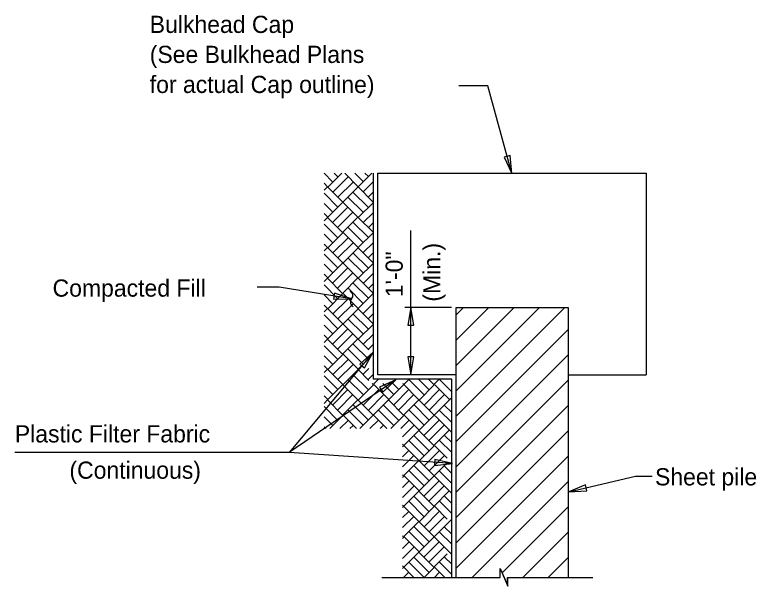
# Model space of a CAD drawing. Extents: x 0.4 to 30.4, y 0.1 to 19.4.
# Drawn here: x 8.54 to 15.06, y 14.4 to 19.42 of the extents above; entities that cross this region are included whole.
import ezdxf

# ---------------------------------------------------------------- set-up
doc = ezdxf.new("R2010")
doc.units = 0
for name, color, linetype in [('Dimension', 7, 'Continuous'), ('Miscellaneous', 7, 'Continuous'), ('Rebar', 7, 'Continuous'), ('SheetPileConc', 7, 'Continuous'), ('SheetPileConc_h', 7, 'Continuous'), ('TextStructures', 7, 'Continuous')]:
    doc.layers.add(name, color=color, linetype=linetype)

msp = doc.modelspace()

# ---------------------------------------------------------------- linework, layer by layer
at = {"layer": 'Dimension'}
for p, q in [((12.0243, 16.2579), (12.0243, 17.526)), ((12.3831, 16.8485), (11.9719, 16.8485)), ((11.8922, 16.2141), (10.9542, 15.5723)), ((12.3913, 15.4765), (10.9542, 15.5723)), ((11.7699, 14.4758), (12.738, 14.4758)), ((12.9487, 14.4758), (13.6252, 14.4758))]:
    msp.add_line(p, q, dxfattribs=at)
for points in [[(12.913, 18.0264), (12.7019, 18.7989), (12.4481, 18.7989)], [(11.5034, 16.9244), (10.8661, 17.0282), (10.6716, 17.0282)], [(11.6942, 16.4565), (10.9542, 15.5723), (8.5393, 15.5723)], [(13.4152, 15.2266), (14.0033, 15.3663), (14.1471, 15.3663)], [(12.738, 14.4758), (12.8099, 14.4758), (12.8099, 14.5539), (12.8768, 14.4028), (12.8768, 14.4758), (12.9487, 14.4758)], [(12.7383, 14.4758), (12.8108, 14.4758), (12.8108, 14.5533), (12.8446, 14.4758), (12.8783, 14.3983), (12.8783, 14.4758), (12.9508, 14.4758)]]:
    msp.add_lwpolyline(points, dxfattribs=at)
for points in [[(12.913, 18.0264), (12.8979, 18.1841), (12.8468, 18.1703)], [(11.5034, 16.9244), (11.3535, 16.9757), (11.345, 16.9234)], [(12.0243, 16.8485), (11.9978, 16.6923), (12.0507, 16.6923)], [(11.6942, 16.4565), (11.5762, 16.3508), (11.6176, 16.3178)], [(12.0243, 16.2579), (12.0507, 16.4141), (11.9978, 16.4141)], [(11.8922, 16.2141), (11.7485, 16.1474), (11.7785, 16.1038)], [(12.3913, 15.4765), (12.2372, 15.513), (12.2338, 15.4601)], [(13.4152, 15.2267), (13.5733, 15.2372), (13.561, 15.2886)]]:
    msp.add_lwpolyline(points, close=True, dxfattribs=at)
for centre, start, end in [((11.4742, 16.9527), 316.04656, 67.77378), ((11.5327, 16.8962), 136.04656, 247.77378)]:
    msp.add_arc(centre, 0.0406, start, end, dxfattribs=at)
at = {"layer": 'Miscellaneous'}
for p, q in [((11.2621, 18.0293), (11.3361, 17.9553)), ((11.4162, 18.0298), (11.2947, 17.9082)), ((11.3499, 18.0298), (11.3803, 17.9994)), ((11.5624, 17.9114), (11.444, 18.0298)), ((11.6065, 17.9555), (11.5323, 18.0298)), ((11.6808, 18.0298), (11.5624, 17.9114)), ((11.6507, 17.9998), (11.6208, 18.0298)), ((11.4716, 17.9966), (11.3389, 17.8639)), ((11.5157, 17.9524), (11.383, 17.8198)), ((11.6952, 17.9559), (11.6065, 17.8673)), ((11.2919, 17.911), (11.2621, 17.9408)), ((11.2919, 17.911), (11.2621, 17.8812)), ((11.5594, 17.6434), (11.2947, 17.9082)), ((11.5596, 17.9086), (11.2948, 17.6438)), ((11.5596, 17.9086), (11.6952, 17.773)), ((11.3832, 17.7322), (11.2621, 17.8533)), ((11.4712, 17.8202), (11.6037, 17.6877)), ((11.5153, 17.8643), (11.6478, 17.7318)), ((11.6952, 17.8673), (11.6506, 17.8231)), ((11.3389, 17.688), (11.2621, 17.7648)), ((11.6952, 17.7736), (11.5622, 17.6406)), ((11.471, 17.7318), (11.3389, 17.5997)), ((11.5152, 17.6877), (11.383, 17.5556)), ((11.6952, 17.6851), (11.6065, 17.5963)), ((11.2948, 17.6438), (11.2621, 17.6766)), ((11.292, 17.641), (11.2621, 17.6111)), ((11.292, 17.641), (11.4246, 17.5085)), ((11.5594, 17.6434), (11.4273, 17.5113)), ((11.6952, 17.5077), (11.5622, 17.6406)), ((11.2621, 17.5824), (11.3803, 17.4643)), ((11.6065, 17.4204), (11.4742, 17.5526)), ((11.6507, 17.4647), (11.5185, 17.5969)), ((11.6952, 17.5964), (11.6506, 17.5522)), ((11.2621, 17.4942), (11.3361, 17.4201)), ((11.4273, 17.5057), (11.2947, 17.3731)), ((11.5624, 17.3762), (11.4301, 17.5085)), ((11.6952, 17.5091), (11.5624, 17.3762)), ((11.4716, 17.4614), (11.3389, 17.3288)), ((11.6952, 17.4209), (11.6065, 17.3321)), ((11.2919, 17.3758), (11.2621, 17.4056)), ((11.2919, 17.3758), (11.2621, 17.3461)), ((11.5594, 17.1083), (11.2947, 17.3731)), ((11.5596, 17.3735), (11.2948, 17.1087)), ((11.5157, 17.4173), (11.383, 17.2847)), ((11.5596, 17.3735), (11.6952, 17.2379)), ((11.3832, 17.1971), (11.2621, 17.3182)), ((11.5153, 17.3292), (11.6478, 17.1967)), ((11.6952, 17.3322), (11.6506, 17.288)), ((11.3389, 17.1529), (11.2621, 17.2297)), ((11.4712, 17.2851), (11.6037, 17.1525)), ((11.6952, 17.2385), (11.5622, 17.1055)), ((11.471, 17.1967), (11.3389, 17.0646)), ((11.2948, 17.1087), (11.2621, 17.1414)), ((11.292, 17.1059), (11.2621, 17.076)), ((11.292, 17.1059), (11.4246, 16.9734)), ((11.5152, 17.1525), (11.383, 17.0205)), ((11.5594, 17.1083), (11.4273, 16.9762)), ((11.6952, 16.9725), (11.5622, 17.1055)), ((11.6952, 17.1499), (11.6065, 17.0612)), ((11.2621, 17.0473), (11.3803, 16.9291)), ((11.6507, 16.9295), (11.5185, 17.0618)), ((11.6952, 17.0613), (11.6506, 17.0171)), ((11.4273, 16.9706), (11.2947, 16.8379)), ((11.5624, 16.8411), (11.4301, 16.9734)), ((11.6065, 16.8853), (11.4742, 17.0175)), ((11.6945, 16.9732), (11.5624, 16.8411)), ((11.2621, 16.9591), (11.3361, 16.885)), ((11.4716, 16.9263), (11.3389, 16.7937)), ((11.2919, 16.8407), (11.2621, 16.8705)), ((11.2919, 16.8407), (11.2621, 16.8109)), ((11.5594, 16.5732), (11.2947, 16.8379)), ((11.5596, 16.8384), (11.2948, 16.5736)), ((11.5157, 16.8822), (11.383, 16.7495)), ((11.5596, 16.8384), (11.6952, 16.7027)), ((11.6952, 16.8858), (11.6065, 16.797)), ((12.4236, 16.5612), (12.7109, 16.8485)), ((12.4236, 16.3385), (12.9336, 16.8485)), ((12.4236, 16.1158), (13.1564, 16.8485)), ((12.4236, 15.8931), (13.3791, 16.8485)), ((12.4236, 16.7839), (12.4882, 16.8485)), ((11.3832, 16.662), (11.2621, 16.7831)), ((11.5153, 16.7941), (11.6478, 16.6616)), ((11.6952, 16.7971), (11.6506, 16.7529)), ((11.4712, 16.75), (11.6037, 16.6174)), ((11.6949, 16.703), (11.5622, 16.5704)), ((11.3389, 16.6177), (11.2621, 16.6946)), ((11.471, 16.6616), (11.3389, 16.5295)), ((12.4236, 15.6703), (13.408, 16.6547)), ((11.2948, 16.5736), (11.2621, 16.6063)), ((11.5152, 16.6174), (11.383, 16.4853)), ((11.5594, 16.5732), (11.4273, 16.441)), ((11.6952, 16.6148), (11.6065, 16.5261)), ((11.292, 16.5708), (11.2621, 16.5409)), ((11.2621, 16.5122), (11.3803, 16.394)), ((11.292, 16.5708), (11.4246, 16.4383)), ((11.6507, 16.3944), (11.5185, 16.5267)), ((11.6559, 16.4768), (11.5622, 16.5704)), ((11.6952, 16.5262), (11.6506, 16.482)), ((11.6065, 16.3501), (11.4742, 16.4824)), ((11.2621, 16.4239), (11.3361, 16.3499)), ((11.4273, 16.4355), (11.2947, 16.3028)), ((11.4716, 16.3912), (11.3389, 16.2585)), ((11.5624, 16.306), (11.4301, 16.4383)), ((11.6559, 16.3995), (11.5624, 16.306)), ((12.4236, 15.4475), (13.408, 16.4319)), ((11.2919, 16.3056), (11.2621, 16.3354)), ((11.5157, 16.3471), (11.383, 16.2144)), ((11.2919, 16.3056), (11.2621, 16.2758)), ((11.3832, 16.1269), (11.2621, 16.248)), ((11.5594, 16.038), (11.2947, 16.3028)), ((11.5596, 16.3032), (11.2948, 16.0384)), ((11.5153, 16.2589), (11.6478, 16.1264)), ((11.5596, 16.3032), (11.6559, 16.207)), ((11.6559, 16.3112), (11.6065, 16.2619)), ((11.6952, 16.2619), (11.6506, 16.2178)), ((11.4712, 16.2148), (11.6037, 16.0823)), ((11.7396, 16.2185), (11.6949, 16.1735)), ((12.01, 16.2185), (11.8299, 16.0384)), ((12.0026, 16.2185), (12.1388, 16.0823)), ((12.0909, 16.2185), (12.1829, 16.1264)), ((12.1794, 16.2185), (12.2272, 16.1707)), ((12.2751, 16.2185), (12.23, 16.1735)), ((12.3842, 16.1074), (12.2733, 16.2185)), ((12.4236, 15.2248), (13.408, 16.2092)), ((11.3389, 16.0826), (11.2621, 16.1594)), ((11.471, 16.1264), (11.3389, 15.9943)), ((11.6949, 16.1679), (11.5622, 16.0353)), ((11.7391, 16.1236), (11.6065, 15.991)), ((11.6837, 16.1792), (11.6921, 16.1707)), ((11.8299, 16.0384), (11.6977, 16.1707)), ((11.874, 16.0826), (11.7775, 16.1792)), ((11.9183, 16.1269), (11.866, 16.1792)), ((12.0062, 16.1264), (11.874, 15.9943)), ((12.0946, 16.038), (11.9534, 16.1792)), ((12.23, 16.1679), (12.0974, 16.0353)), ((12.2743, 16.1236), (12.1416, 15.991)), ((12.365, 16.0385), (12.2328, 16.1707)), ((11.2948, 16.0384), (11.2621, 16.0711)), ((11.5152, 16.0823), (11.383, 15.9502)), ((11.7833, 16.0795), (11.6506, 15.9469)), ((12.0503, 16.0823), (11.9182, 15.9502)), ((12.3842, 16.0577), (12.0975, 15.7709)), ((12.3184, 16.0795), (12.1857, 15.9469)), ((11.292, 16.0357), (11.2621, 16.0058)), ((11.292, 16.0357), (11.4246, 15.9031)), ((11.5594, 16.038), (11.4273, 15.9059)), ((11.6507, 15.8593), (11.5185, 15.9916)), ((11.8121, 15.7854), (11.5622, 16.0353)), ((11.8272, 16.0357), (11.5768, 15.7854)), ((11.7829, 15.9914), (11.9154, 15.8589)), ((11.8272, 16.0357), (11.9597, 15.9031)), ((12.0946, 16.038), (11.9624, 15.9059)), ((12.1859, 15.8593), (12.0536, 15.9916)), ((12.3842, 15.7483), (12.0974, 16.0353)), ((12.318, 15.9914), (12.3842, 15.9251)), ((12.4236, 15.0021), (13.408, 15.9865)), ((11.2621, 15.977), (11.3803, 15.8589)), ((11.6065, 15.815), (11.4742, 15.9473)), ((11.7387, 15.9473), (11.8713, 15.8147)), ((12.1416, 15.815), (12.0093, 15.9473)), ((12.2739, 15.9473), (12.3842, 15.8368)), ((11.2621, 15.8888), (11.3361, 15.8147)), ((11.4273, 15.9004), (11.3124, 15.7854)), ((11.4716, 15.8561), (11.4009, 15.7854)), ((11.5478, 15.7854), (11.4301, 15.9031)), ((11.7386, 15.8589), (11.6651, 15.7854)), ((11.9624, 15.9004), (11.8475, 15.7854)), ((12.0067, 15.8561), (11.9361, 15.7854)), ((12.0975, 15.7709), (11.9652, 15.9031)), ((12.2737, 15.8589), (12.1416, 15.7268)), ((11.2769, 15.7854), (11.2621, 15.8003)), ((11.5157, 15.812), (11.4891, 15.7854)), ((11.7827, 15.8147), (11.7534, 15.7854)), ((12.0509, 15.812), (11.9512, 15.7122)), ((12.3178, 15.8147), (12.1857, 15.6826)), ((12.0947, 15.7681), (11.9512, 15.6245)), ((12.0947, 15.7681), (12.2272, 15.6356)), ((12.3621, 15.7705), (12.23, 15.6384)), ((12.4236, 14.7794), (13.408, 15.7637)), ((12.0063, 15.6797), (12.1388, 15.5472)), ((12.0504, 15.7238), (12.1829, 15.5913)), ((12.3842, 15.5724), (12.2769, 15.6797)), ((12.3842, 15.6609), (12.3212, 15.724)), ((12.0946, 15.5029), (11.9512, 15.6463)), ((12.23, 15.6328), (12.0974, 15.5001)), ((12.3449, 15.5235), (12.2328, 15.6356)), ((12.0062, 15.5913), (11.9512, 15.5363)), ((12.0503, 15.5472), (11.9512, 15.448)), ((12.2743, 15.5885), (12.1416, 15.4559)), ((12.3184, 15.5444), (12.1857, 15.4117)), ((12.4236, 14.5566), (13.408, 15.541)), ((12.0946, 15.5029), (11.9624, 15.3708)), ((12.3842, 15.2132), (12.0974, 15.5001)), ((12.3449, 15.4832), (12.0975, 15.2358)), ((12.1416, 15.2799), (12.0093, 15.4122)), ((12.1859, 15.3242), (12.0536, 15.4564)), ((12.2739, 15.4122), (12.3842, 15.3017)), ((12.318, 15.4563), (12.3842, 15.3899)), ((11.9512, 15.3766), (11.9597, 15.368)), ((11.9624, 15.3653), (11.9512, 15.3539)), ((12.0975, 15.2358), (11.9652, 15.368)), ((12.0067, 15.321), (11.9512, 15.2654)), ((12.0509, 15.2768), (11.9512, 15.1771)), ((12.2737, 15.3237), (12.1416, 15.1917)), ((12.3178, 15.2796), (12.1857, 15.1475)), ((12.5655, 14.4758), (13.408, 15.3183)), ((12.0947, 15.233), (11.9512, 15.0894)), ((12.0947, 15.233), (12.2272, 15.1005)), ((12.3621, 15.2354), (12.23, 15.1032)), ((12.0063, 15.1446), (12.1388, 15.0121)), ((12.0504, 15.1887), (12.1829, 15.0562)), ((12.3842, 15.0372), (12.2769, 15.1446)), ((12.3842, 15.1258), (12.3212, 15.1888)), ((12.0946, 14.9678), (11.9512, 15.1112)), ((12.23, 15.0976), (12.0974, 14.965)), ((12.3449, 14.9884), (12.2328, 15.1005)), ((12.8273, 14.5148), (13.408, 15.0955)), ((12.0062, 15.0562), (11.9512, 15.0012)), ((12.0503, 15.0121), (11.9512, 14.9129)), ((12.2743, 15.0534), (12.1416, 14.9207)), ((12.3184, 15.0093), (12.1857, 14.8766)), ((12.0946, 14.9678), (11.9624, 14.8357)), ((12.3842, 14.6781), (12.0974, 14.965)), ((12.3842, 14.9874), (12.0975, 14.7006)), ((12.1416, 14.7448), (12.0093, 14.877)), ((12.1859, 14.7891), (12.0536, 14.9213)), ((12.2739, 14.877), (12.3842, 14.7666)), ((12.318, 14.9211), (12.3842, 14.8549)), ((11.9512, 14.8414), (11.9597, 14.8329)), ((11.9624, 14.8301), (11.9512, 14.8188)), ((12.0975, 14.7006), (11.9652, 14.8329)), ((13.011, 14.4758), (13.408, 14.8728)), ((12.0067, 14.7858), (11.9512, 14.7303)), ((12.2737, 14.7886), (12.1416, 14.6565)), ((12.0509, 14.7417), (11.9512, 14.642)), ((12.0947, 14.6979), (11.9512, 14.5543)), ((12.0947, 14.6979), (12.2272, 14.5653)), ((12.3178, 14.7445), (12.1857, 14.6124)), ((12.3449, 14.683), (12.23, 14.5681)), ((12.0504, 14.6536), (12.1829, 14.5211)), ((12.3842, 14.5907), (12.3212, 14.6537)), ((13.2338, 14.4758), (13.408, 14.65)), ((12.0514, 14.4758), (11.9512, 14.5761)), ((12.0063, 14.6095), (12.1388, 14.4769)), ((12.23, 14.5625), (12.1432, 14.4758)), ((12.3224, 14.4758), (12.2328, 14.5653)), ((12.3842, 14.5021), (12.2769, 14.6095)), ((12.0062, 14.5211), (11.9609, 14.4758)), ((12.2743, 14.5183), (12.2318, 14.4758)), ((12.0503, 14.4769), (12.0491, 14.4758))]:
    msp.add_line(p, q, dxfattribs=at)
at = {"layer": 'Rebar'}
for p, q in [((11.6952, 16.2185), (11.6952, 18.0298)), ((12.3842, 16.2185), (11.6952, 16.2185)), ((12.3842, 14.4758), (12.3842, 16.2185))]:
    msp.add_line(p, q, dxfattribs=at)
at = {"layer": 'SheetPileConc'}
for p, q in [((12.4236, 14.4758), (12.4236, 16.8485)), ((12.4236, 16.8485), (13.408, 16.8485)), ((13.408, 16.8485), (13.408, 14.4758))]:
    msp.add_line(p, q, dxfattribs=at)
at = {"layer": 'SheetPileConc_h'}
for p, q in [((11.7346, 16.2579), (11.7346, 18.0298)), ((11.7346, 18.0298), (14.0971, 18.0298)), ((14.0971, 18.0298), (14.0971, 16.2579)), ((12.4237, 16.2579), (11.7346, 16.2579)), ((13.408, 16.2579), (14.0971, 16.2579))]:
    msp.add_line(p, q, dxfattribs=at)

# ---------------------------------------------------------------- texts
at = {"layer": 'Dimension'}
for s, p in [('Bulkhead Cap', (9.7268, 19.2632)), ('(See Bulkhead Plans', (9.7268, 18.9992)), ('for actual Cap outline)', (9.7268, 18.7352)), ('Plastic Filter Fabric', (8.5394, 15.6622)), ('(Continuous)', (9.0199, 15.343))]:
    msp.add_text(s, height=0.1512, dxfattribs=at).set_placement(p)
at = {"layer": 'TextStructures'}
for s, p in [('(Min.)', (12.2848, 16.9001)), ('1\'-0"', (11.9536, 16.9394))]:
    msp.add_text(s, height=0.1512, rotation=90, dxfattribs=at).set_placement(p)
for s, p in [('Compacted Fill', (8.8715, 16.9442)), ('Sheet pile', (14.1736, 15.2842))]:
    msp.add_text(s, height=0.1512, dxfattribs=at).set_placement(p)

doc.saveas('drawing.dxf')
